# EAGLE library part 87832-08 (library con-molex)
Milli-Grid Header 2.00mm (.079") Pitch
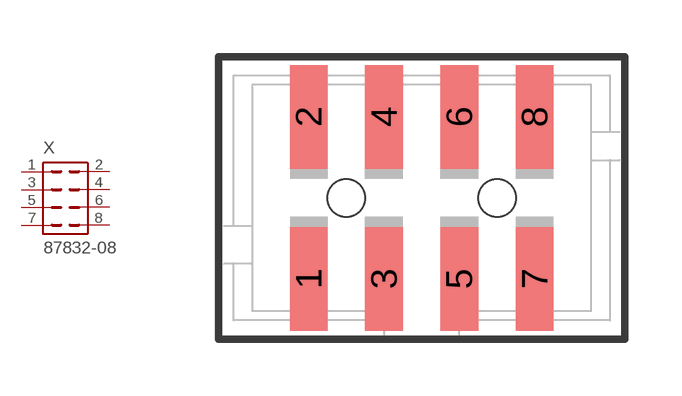
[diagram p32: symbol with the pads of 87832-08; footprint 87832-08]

Designator prefix X

## 87832-08 (OC_FARNELL: unknown; OC_NEWARK: unknown)  [87832-08]
1  1  pas
2  2  pas
3  3  pas
4  4  pas
5  5  pas
6  6  pas
7  7  pas
8  8  pas

## Footprint 87832-08 (pad centres in mm)
PCB Headers 2.00mm (.079") Pitch Milli-Grid Header, Vertical, Shrouded
smd 1 x 2.75: 1 -3,-2.15; 2 -3,2.15; 3 -1,-2.15; 4 -1,2.15; 5 1,-2.15; 6 1,2.15; 7 3,-2.15; 8 3,2.15
hole 1 at -2,0
hole 1 at 2,0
